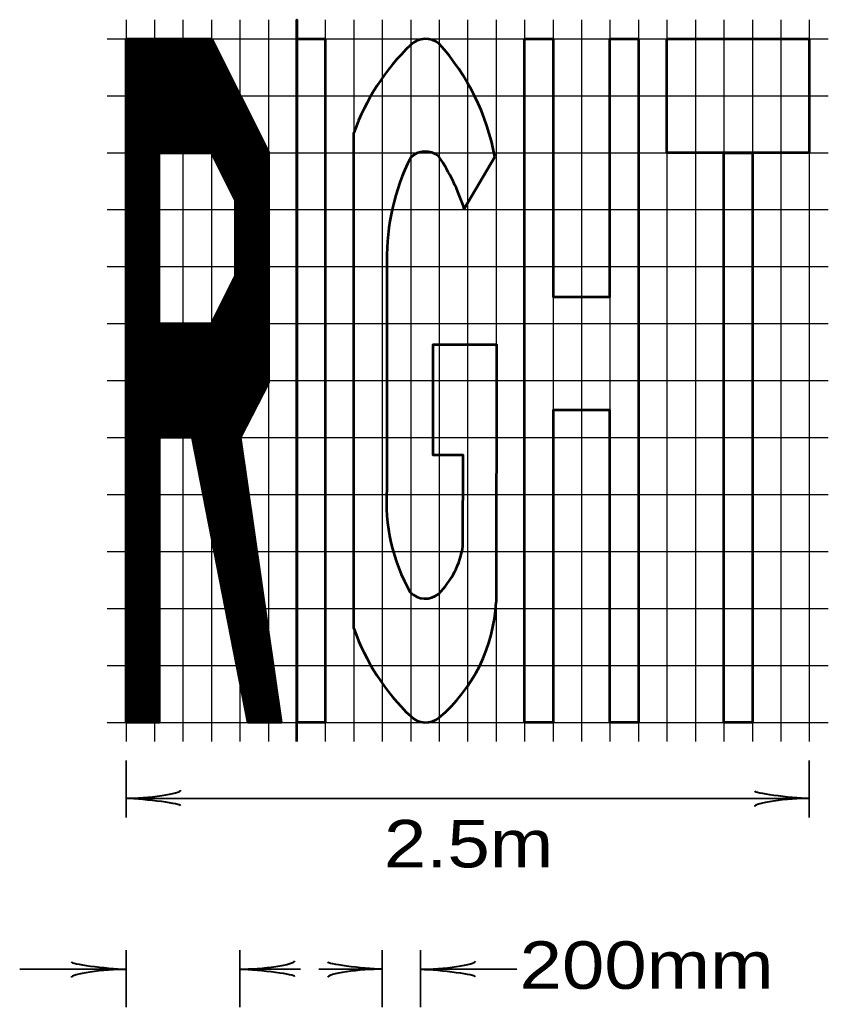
# Model space of a CAD drawing. Extents: x -96 to 617, y -65 to 388.
# Drawn here: x -13.8 to 28.8, y 261.3 to 313.3 of the extents above; entities that cross this region are included whole.
import ezdxf

# ---------------------------------------------------------------- set-up
doc = ezdxf.new("R2010")
doc.units = 0
doc.layers.add('1', color=7, linetype='Continuous', lineweight=53)

msp = doc.modelspace()

# ---------------------------------------------------------------- linework, layer by layer
at = {"layer": '1', "lineweight": 25}
for p, q in [((-8.21, 313.267), (-8.21, 275.267)), ((-6.71, 313.267), (-6.71, 275.267)), ((-5.21, 313.267), (-5.21, 275.267)), ((-3.71, 313.267), (-3.71, 275.267)), ((-2.21, 313.267), (-2.21, 275.267)), ((-0.71, 313.267), (-0.71, 275.267)), ((0.79, 313.267), (0.79, 275.267)), ((2.29, 313.267), (2.29, 275.267)), ((3.79, 313.267), (3.79, 275.267)), ((5.29, 313.267), (5.29, 275.267)), ((6.79, 313.267), (6.79, 275.267)), ((8.29, 313.267), (8.29, 275.267)), ((9.79, 313.267), (9.79, 275.267)), ((11.29, 313.267), (11.29, 275.267)), ((12.79, 313.267), (12.79, 275.267)), ((14.29, 313.267), (14.29, 275.267)), ((15.79, 313.267), (15.79, 275.267)), ((17.29, 313.267), (17.29, 275.267)), ((18.79, 313.267), (18.79, 275.267)), ((20.29, 313.267), (20.29, 275.267)), ((21.79, 313.267), (21.79, 275.267)), ((23.29, 313.267), (23.29, 275.267)), ((24.79, 313.267), (24.79, 275.267)), ((26.29, 313.267), (26.29, 275.267)), ((27.79, 313.267), (27.79, 275.267)), ((-9.21, 312.267), (28.79, 312.267)), ((-9.21, 309.267), (28.79, 309.267)), ((-9.21, 306.267), (28.79, 306.267)), ((-9.21, 303.267), (28.79, 303.267)), ((-9.21, 300.267), (28.79, 300.267)), ((-9.21, 297.267), (28.79, 297.267)), ((-9.21, 294.267), (28.79, 294.267)), ((-9.21, 291.267), (28.79, 291.267)), ((-9.21, 288.267), (28.79, 288.267)), ((-9.21, 285.267), (28.79, 285.267)), ((-9.21, 282.267), (28.79, 282.267)), ((-9.21, 279.267), (28.79, 279.267)), ((-9.21, 276.267), (28.79, 276.267))]:
    msp.add_line(p, q, dxfattribs=at)
at = {"layer": '1'}
for p, q in [((-8.21, 312.122), (-8.064, 312.267)), ((-8.21, 311.945), (-7.888, 312.267)), ((-8.21, 311.769), (-7.711, 312.267)), ((-8.21, 311.592), (-7.534, 312.267)), ((-8.21, 311.415), (-7.357, 312.267)), ((-8.21, 311.238), (-7.181, 312.267)), ((-8.21, 311.061), (-7.004, 312.267)), ((-8.21, 310.885), (-6.827, 312.267)), ((-8.21, 310.708), (-6.65, 312.267)), ((-8.21, 310.531), (-6.473, 312.267)), ((-8.21, 310.354), (-6.297, 312.267)), ((-8.21, 310.178), (-6.12, 312.267)), ((-8.21, 310.001), (-5.943, 312.267)), ((-8.21, 309.824), (-5.766, 312.267)), ((-8.21, 309.647), (-5.59, 312.267)), ((-8.21, 309.47), (-5.413, 312.267)), ((-8.21, 309.294), (-5.236, 312.267)), ((-8.21, 309.117), (-5.059, 312.267)), ((-8.21, 308.94), (-4.882, 312.267)), ((-8.21, 308.763), (-4.706, 312.267)), ((-8.21, 308.587), (-4.529, 312.267)), ((-8.21, 308.41), (-4.352, 312.267)), ((-8.21, 308.233), (-4.175, 312.267)), ((-8.21, 308.056), (-3.999, 312.267)), ((-8.21, 307.879), (-3.822, 312.267)), ((-8.21, 307.703), (-3.688, 312.224)), ((-8.21, 307.526), (-3.629, 312.107)), ((0.79, 312.267), (0.79, 276.267)), ((-8.21, 307.349), (-3.569, 311.989)), ((-8.21, 307.172), (-3.51, 311.872)), ((-8.21, 306.996), (-3.451, 311.754)), ((-8.21, 306.819), (-3.392, 311.637)), ((-8.21, 306.642), (-3.332, 311.519)), ((-8.21, 306.465), (-3.273, 311.402)), ((-8.21, 306.288), (-3.214, 311.284)), ((-8.21, 306.112), (-3.155, 311.167)), ((-8.21, 305.935), (-3.095, 311.049)), ((-8.21, 305.758), (-3.036, 310.932)), ((-8.21, 305.581), (-2.977, 310.814)), ((-8.21, 305.405), (-2.918, 310.697)), ((-8.21, 305.228), (-2.858, 310.579)), ((-8.21, 305.051), (-2.799, 310.462)), ((-8.21, 304.874), (-2.74, 310.344)), ((-8.21, 304.697), (-2.68, 310.227)), ((-8.21, 304.521), (-2.621, 310.109)), ((-6.29, 306.264), (-2.562, 309.991)), ((-6.114, 306.262), (-2.503, 309.874)), ((-5.939, 306.261), (-2.443, 309.757)), ((-5.764, 306.26), (-2.384, 309.639)), ((-5.588, 306.258), (-2.325, 309.522)), ((-5.413, 306.257), (-2.266, 309.404)), ((-5.237, 306.255), (-2.206, 309.286)), ((-5.062, 306.254), (-2.147, 309.169)), ((-4.887, 306.252), (-2.088, 309.051)), ((-4.711, 306.251), (-2.029, 308.934)), ((-4.536, 306.25), (-1.969, 308.816)), ((-4.361, 306.248), (-1.91, 308.699)), ((-4.185, 306.247), (-1.851, 308.581)), ((-4.01, 306.245), (-1.792, 308.464)), ((-3.835, 306.244), (-1.732, 308.346)), ((-3.674, 306.228), (-1.673, 308.229)), ((-3.615, 306.11), (-1.614, 308.111)), ((-3.557, 305.991), (-1.554, 307.994)), ((-3.499, 305.873), (-1.495, 307.876)), ((-3.44, 305.755), (-1.436, 307.759)), ((-3.382, 305.636), (-1.377, 307.641)), ((-3.323, 305.518), (-1.317, 307.524)), ((-3.265, 305.399), (-1.258, 307.406)), ((-3.207, 305.281), (-1.199, 307.289)), ((-3.148, 305.163), (-1.14, 307.171)), ((-3.09, 305.044), (-1.08, 307.054)), ((-3.031, 304.926), (-1.021, 306.936)), ((-2.973, 304.808), (-0.962, 306.819)), ((3.79, 281.219), (3.79, 307.307)), ((-2.915, 304.689), (-0.903, 306.701)), ((-2.856, 304.571), (-0.843, 306.584)), ((-2.798, 304.452), (-0.784, 306.466)), ((-2.739, 304.334), (-0.725, 306.349)), ((-8.21, 304.344), (-6.46, 306.094)), ((-8.21, 304.167), (-6.46, 305.917)), ((-2.681, 304.216), (-0.695, 306.201)), ((-2.623, 304.097), (-0.695, 306.025)), ((-2.564, 303.979), (-0.695, 305.848)), ((11.223, 306.057), (9.615, 303.315)), ((-8.21, 303.99), (-6.46, 305.74)), ((-8.21, 303.814), (-6.46, 305.564)), ((-8.21, 303.637), (-6.46, 305.387)), ((-2.506, 303.861), (-0.695, 305.671)), ((-2.46, 303.73), (-0.695, 305.494)), ((-2.46, 303.553), (-0.695, 305.317)), ((-8.21, 303.46), (-6.46, 305.21)), ((-8.21, 303.283), (-6.46, 305.033)), ((-8.21, 303.106), (-6.46, 304.856)), ((-2.46, 303.376), (-0.695, 305.141)), ((-2.46, 303.2), (-0.695, 304.964)), ((-2.46, 303.023), (-0.695, 304.787)), ((-8.21, 302.93), (-6.46, 304.68)), ((-8.21, 302.753), (-6.46, 304.503)), ((-8.21, 302.576), (-6.46, 304.326)), ((-2.46, 302.846), (-0.695, 304.61)), ((-2.46, 302.669), (-0.695, 304.434)), ((-2.46, 302.493), (-0.695, 304.257)), ((-8.21, 302.399), (-6.46, 304.149)), ((-8.21, 302.223), (-6.46, 303.973)), ((-8.21, 302.046), (-6.46, 303.796)), ((-2.46, 302.316), (-0.695, 304.08)), ((-2.46, 302.139), (-0.695, 303.903)), ((-2.46, 301.962), (-0.695, 303.726)), ((-8.21, 301.869), (-6.46, 303.619)), ((-8.21, 301.692), (-6.46, 303.442)), ((-8.21, 301.515), (-6.46, 303.265)), ((-2.46, 301.785), (-0.695, 303.55)), ((-2.46, 301.609), (-0.695, 303.373)), ((-2.46, 301.432), (-0.695, 303.196)), ((-8.21, 301.339), (-6.46, 303.089)), ((-8.21, 301.162), (-6.46, 302.912)), ((-8.21, 300.985), (-6.46, 302.735)), ((-2.46, 301.255), (-0.695, 303.019)), ((-2.46, 301.078), (-0.695, 302.843)), ((-2.46, 300.901), (-0.695, 302.666)), ((-8.21, 300.808), (-6.46, 302.558)), ((-8.21, 300.632), (-6.46, 302.382)), ((-8.21, 300.455), (-6.46, 302.205)), ((-2.46, 300.725), (-0.695, 302.489)), ((-2.46, 300.548), (-0.695, 302.312)), ((-2.46, 300.371), (-0.695, 302.135)), ((-8.21, 300.278), (-6.46, 302.028)), ((-8.21, 300.101), (-6.46, 301.851)), ((-8.21, 299.924), (-6.46, 301.674)), ((-2.46, 300.194), (-0.695, 301.959)), ((-2.46, 300.018), (-0.695, 301.782)), ((-2.46, 299.841), (-0.695, 301.605)), ((-8.21, 299.748), (-6.46, 301.498)), ((-8.21, 299.571), (-6.46, 301.321)), ((-8.21, 299.394), (-6.46, 301.144)), ((-2.731, 299.216), (-0.695, 301.252)), ((-2.559, 299.564), (-0.695, 301.428)), ((-8.21, 299.217), (-6.46, 300.967)), ((-8.21, 299.041), (-6.46, 300.791)), ((-8.21, 298.864), (-6.46, 300.614)), ((-3.245, 298.172), (-0.695, 300.721)), ((-3.073, 298.52), (-0.695, 300.898)), ((-2.902, 298.868), (-0.695, 301.075)), ((-8.21, 298.687), (-6.46, 300.437)), ((-8.21, 298.51), (-6.46, 300.26)), ((-8.21, 292.677), (-0.695, 300.191)), ((-8.21, 298.334), (-6.46, 300.084)), ((-3.587, 297.476), (-0.695, 300.368)), ((-3.416, 297.824), (-0.695, 300.544)), ((5.54, 300.557), (5.54, 288.557)), ((-8.21, 292.5), (-0.695, 300.014)), ((-8.21, 298.157), (-6.46, 299.907)), ((-8.21, 292.323), (-0.695, 299.837)), ((-8.21, 297.98), (-6.46, 299.73)), ((-8.21, 292.146), (-0.695, 299.661)), ((-8.21, 297.803), (-6.46, 299.553)), ((-8.21, 291.97), (-0.695, 299.484)), ((-8.21, 297.626), (-6.46, 299.376)), ((-8.21, 291.793), (-0.695, 299.307)), ((-8.21, 297.45), (-6.46, 299.2)), ((-8.21, 291.616), (-0.695, 299.13)), ((-8.21, 297.273), (-6.46, 299.023)), ((-8.21, 291.439), (-0.695, 298.954)), ((-8.21, 297.096), (-6.46, 298.846)), ((-8.21, 291.262), (-0.695, 298.777)), ((-8.21, 296.919), (-6.46, 298.669)), ((-8.21, 291.086), (-0.695, 298.6)), ((-8.21, 296.743), (-6.46, 298.493)), ((-8.21, 290.909), (-0.695, 298.423)), ((-8.21, 296.566), (-6.46, 298.316)), ((-8.21, 290.732), (-0.695, 298.246)), ((-8.21, 296.389), (-6.46, 298.139)), ((-8.21, 290.555), (-0.695, 298.07)), ((-8.21, 296.212), (-6.46, 297.962)), ((-8.21, 290.379), (-0.695, 297.893)), ((-8.21, 296.035), (-6.46, 297.785)), ((-8.21, 290.202), (-0.695, 297.716)), ((-8.21, 295.859), (-6.46, 297.609)), ((-8.21, 290.025), (-0.695, 297.539)), ((-8.21, 295.682), (-6.46, 297.432)), ((-8.21, 289.848), (-0.695, 297.363)), ((-8.21, 295.505), (-6.449, 297.265)), ((-8.21, 295.328), (-6.273, 297.264)), ((-8.21, 295.151), (-6.098, 297.263)), ((-8.21, 294.975), (-5.922, 297.262)), ((-8.21, 294.798), (-5.747, 297.261)), ((-8.21, 294.621), (-5.571, 297.26)), ((-8.21, 294.444), (-5.395, 297.259)), ((-8.21, 294.268), (-5.22, 297.258)), ((-8.21, 294.091), (-5.044, 297.257)), ((-8.21, 293.914), (-4.868, 297.255)), ((-8.21, 293.737), (-4.693, 297.254)), ((-8.21, 293.56), (-4.517, 297.253)), ((-8.21, 293.384), (-4.341, 297.252)), ((-8.21, 293.207), (-4.166, 297.251)), ((-8.21, 293.03), (-3.99, 297.25)), ((-8.21, 292.853), (-3.814, 297.249)), ((-8.21, 289.671), (-0.695, 297.186)), ((-6.437, 291.267), (-0.695, 297.009)), ((-6.26, 291.267), (-0.695, 296.832)), ((-6.083, 291.267), (-0.695, 296.655)), ((-5.907, 291.267), (-0.695, 296.479)), ((-5.73, 291.267), (-0.695, 296.302)), ((-5.553, 291.267), (-0.695, 296.125)), ((-5.376, 291.267), (-0.695, 295.948)), ((-5.2, 291.267), (-0.695, 295.772)), ((-5.023, 291.267), (-0.695, 295.595)), ((-4.846, 291.267), (-0.695, 295.418)), ((-4.703, 291.233), (-0.695, 295.241)), ((-4.674, 291.086), (-0.695, 295.065)), ((-4.645, 290.938), (-0.695, 294.888)), ((-4.616, 290.79), (-0.695, 294.711)), ((-4.587, 290.642), (-0.695, 294.534)), ((-4.559, 290.494), (-0.695, 294.357)), ((-4.53, 290.346), (-0.695, 294.181)), ((-4.501, 290.198), (-0.871, 293.828)), ((-4.472, 290.05), (-1.062, 293.46)), ((-4.443, 289.902), (-1.253, 293.093)), ((-4.414, 289.755), (-1.443, 292.725)), ((-4.385, 289.607), (-1.634, 292.358)), ((-4.356, 289.459), (-1.825, 291.99)), ((-8.21, 289.495), (-6.46, 291.245)), ((-4.327, 289.311), (-2.016, 291.623)), ((-4.299, 289.163), (-2.195, 291.267)), ((-8.21, 289.318), (-6.46, 291.068)), ((-8.21, 289.141), (-6.46, 290.891)), ((-8.21, 288.964), (-6.46, 290.714)), ((-4.27, 289.015), (-2.173, 291.112)), ((-4.241, 288.867), (-2.151, 290.958)), ((-4.212, 288.719), (-2.128, 290.803)), ((-8.21, 288.788), (-6.46, 290.538)), ((-8.21, 288.611), (-6.46, 290.361)), ((-8.21, 288.434), (-6.46, 290.184)), ((-4.183, 288.572), (-2.106, 290.649)), ((-4.154, 288.424), (-2.084, 290.494)), ((-4.125, 288.276), (-2.061, 290.34)), ((-4.096, 288.128), (-2.039, 290.185)), ((-8.21, 288.257), (-6.46, 290.007)), ((-8.21, 288.08), (-6.46, 289.83)), ((-8.21, 287.904), (-6.46, 289.654)), ((-4.067, 287.98), (-2.017, 290.031)), ((-4.039, 287.832), (-1.994, 289.876)), ((-4.01, 287.684), (-1.972, 289.722)), ((-8.21, 287.727), (-6.46, 289.477)), ((-8.21, 287.55), (-6.46, 289.3)), ((-8.21, 287.373), (-6.46, 289.123)), ((-3.981, 287.536), (-1.95, 289.567)), ((-3.952, 287.388), (-1.927, 289.413)), ((-3.923, 287.24), (-1.905, 289.258)), ((-8.21, 287.197), (-6.46, 288.947)), ((-8.21, 287.02), (-6.46, 288.77)), ((-3.894, 287.093), (-1.883, 289.104)), ((-3.865, 286.945), (-1.861, 288.949)), ((-3.836, 286.797), (-1.838, 288.795)), ((-3.807, 286.649), (-1.816, 288.64)), ((-8.21, 286.843), (-6.46, 288.593)), ((-8.21, 286.666), (-6.46, 288.416)), ((-8.21, 286.489), (-6.46, 288.239)), ((-3.779, 286.501), (-1.794, 288.486)), ((-3.75, 286.353), (-1.771, 288.332)), ((-3.721, 286.205), (-1.749, 288.177)), ((-8.21, 286.313), (-6.46, 288.063)), ((-8.21, 286.136), (-6.46, 287.886)), ((-8.21, 285.959), (-6.46, 287.709)), ((-3.692, 286.057), (-1.727, 288.023)), ((-3.663, 285.909), (-1.704, 287.868)), ((-3.634, 285.762), (-1.682, 287.714)), ((-8.21, 285.782), (-6.46, 287.532)), ((-8.21, 285.606), (-6.46, 287.356)), ((-8.21, 285.429), (-6.46, 287.179)), ((-3.605, 285.614), (-1.66, 287.559)), ((-3.576, 285.466), (-1.637, 287.405)), ((-3.547, 285.318), (-1.615, 287.25)), ((-3.519, 285.17), (-1.593, 287.096)), ((-8.21, 285.252), (-6.46, 287.002)), ((-8.21, 285.075), (-6.46, 286.825)), ((-8.21, 284.899), (-6.46, 286.649)), ((-3.49, 285.022), (-1.571, 286.941)), ((-3.461, 284.874), (-1.548, 286.787)), ((-3.432, 284.726), (-1.526, 286.632)), ((-8.21, 284.722), (-6.46, 286.472)), ((-8.21, 284.545), (-6.46, 286.295)), ((-8.21, 284.368), (-6.46, 286.118)), ((-3.403, 284.578), (-1.504, 286.478)), ((-3.374, 284.431), (-1.481, 286.323)), ((-3.345, 284.283), (-1.459, 286.169)), ((-3.316, 284.135), (-1.437, 286.014)), ((-8.21, 284.191), (-6.46, 285.941)), ((-8.21, 284.015), (-6.46, 285.765)), ((-8.21, 283.838), (-6.46, 285.588)), ((-3.288, 283.987), (-1.414, 285.86)), ((-3.259, 283.839), (-1.392, 285.705)), ((-3.23, 283.691), (-1.37, 285.551)), ((-8.21, 283.661), (-6.46, 285.411)), ((-8.21, 283.484), (-6.46, 285.234)), ((-8.21, 283.308), (-6.46, 285.058)), ((-3.201, 283.543), (-1.347, 285.397)), ((-3.172, 283.395), (-1.325, 285.242)), ((-3.143, 283.247), (-1.303, 285.088)), ((-8.21, 283.131), (-6.46, 284.881)), ((-8.21, 282.954), (-6.46, 284.704)), ((-8.21, 282.777), (-6.46, 284.527)), ((-3.114, 283.1), (-1.281, 284.933)), ((-3.085, 282.952), (-1.258, 284.779)), ((-3.056, 282.804), (-1.236, 284.624)), ((-3.028, 282.656), (-1.214, 284.47)), ((-8.21, 282.6), (-6.46, 284.35)), ((-8.21, 282.424), (-6.46, 284.174)), ((-8.21, 282.247), (-6.46, 283.997)), ((-2.999, 282.508), (-1.191, 284.315)), ((-2.97, 282.36), (-1.169, 284.161)), ((-2.941, 282.212), (-1.147, 284.006)), ((-8.21, 282.07), (-6.46, 283.82)), ((-8.21, 281.893), (-6.46, 283.643)), ((-8.21, 281.716), (-6.46, 283.466)), ((-2.912, 282.064), (-1.125, 283.852)), ((-2.883, 281.916), (-1.102, 283.697)), ((-2.854, 281.769), (-1.08, 283.543)), ((-8.21, 281.54), (-6.46, 283.29)), ((-8.21, 281.363), (-6.46, 283.113)), ((-8.21, 281.186), (-6.46, 282.936)), ((-2.825, 281.621), (-1.058, 283.388)), ((-2.796, 281.473), (-1.035, 283.234)), ((-2.768, 281.325), (-1.013, 283.079)), ((-2.739, 281.177), (-0.991, 282.925)), ((-8.21, 281.009), (-6.46, 282.759)), ((-8.21, 280.833), (-6.46, 282.583)), ((-8.21, 280.656), (-6.46, 282.406)), ((-2.71, 281.029), (-0.968, 282.771)), ((-2.681, 280.881), (-0.946, 282.616)), ((-2.652, 280.733), (-0.924, 282.462)), ((-8.21, 280.479), (-6.46, 282.229)), ((-8.21, 280.302), (-6.46, 282.052)), ((-8.21, 280.125), (-6.46, 281.875)), ((-2.623, 280.585), (-0.901, 282.307)), ((-2.594, 280.438), (-0.879, 282.153)), ((-2.565, 280.29), (-0.857, 281.998)), ((-2.536, 280.142), (-0.835, 281.844)), ((-8.21, 279.949), (-6.46, 281.699)), ((-8.21, 279.772), (-6.46, 281.522)), ((-8.21, 279.595), (-6.46, 281.345)), ((-2.508, 279.994), (-0.812, 281.689)), ((-2.479, 279.846), (-0.79, 281.535)), ((-2.45, 279.698), (-0.768, 281.38)), ((-8.21, 279.418), (-6.46, 281.168)), ((-8.21, 279.242), (-6.46, 280.992)), ((-8.21, 279.065), (-6.46, 280.815)), ((-2.421, 279.55), (-0.745, 281.226)), ((-2.392, 279.402), (-0.723, 281.071)), ((-2.363, 279.254), (-0.701, 280.917)), ((-8.21, 278.888), (-6.46, 280.638)), ((-8.21, 278.711), (-6.46, 280.461)), ((-8.21, 278.534), (-6.46, 280.284)), ((-2.334, 279.107), (-0.678, 280.762)), ((-2.305, 278.959), (-0.656, 280.608)), ((-2.276, 278.811), (-0.634, 280.453)), ((-2.248, 278.663), (-0.611, 280.299)), ((-8.21, 278.358), (-6.46, 280.108)), ((-8.21, 278.181), (-6.46, 279.931)), ((-2.219, 278.515), (-0.589, 280.145)), ((-2.19, 278.367), (-0.567, 279.99)), ((-2.161, 278.219), (-0.544, 279.836)), ((-8.21, 278.004), (-6.46, 279.754)), ((-8.21, 277.827), (-6.46, 279.577)), ((-8.21, 277.651), (-6.46, 279.401)), ((-2.132, 278.071), (-0.522, 279.681)), ((-2.103, 277.923), (-0.5, 279.527)), ((-2.074, 277.776), (-0.478, 279.372)), ((-8.21, 277.474), (-6.46, 279.224)), ((-8.21, 277.297), (-6.46, 279.047)), ((-8.21, 277.12), (-6.46, 278.87)), ((-2.045, 277.628), (-0.455, 279.218)), ((-2.016, 277.48), (-0.433, 279.063)), ((-1.988, 277.332), (-0.411, 278.909)), ((-1.959, 277.184), (-0.388, 278.754)), ((-8.21, 276.943), (-6.46, 278.693)), ((-8.21, 276.767), (-6.46, 278.517)), ((-8.21, 276.59), (-6.46, 278.34)), ((-1.93, 277.036), (-0.366, 278.6)), ((-1.901, 276.888), (-0.344, 278.445)), ((-1.872, 276.74), (-0.322, 278.291)), ((-8.21, 276.413), (-6.46, 278.163)), ((-8.179, 276.267), (-6.46, 277.986)), ((-8.002, 276.267), (-6.46, 277.81)), ((-1.843, 276.592), (-0.299, 278.136)), ((-1.814, 276.445), (-0.277, 277.982)), ((-1.785, 276.297), (-0.255, 277.827)), ((-7.825, 276.267), (-6.46, 277.633)), ((-7.648, 276.267), (-6.46, 277.456)), ((-7.472, 276.267), (-6.46, 277.279)), ((-1.646, 276.26), (-0.232, 277.673)), ((-1.469, 276.26), (-0.21, 277.519)), ((-1.292, 276.26), (-0.188, 277.364)), ((-1.115, 276.26), (-0.165, 277.21)), ((-7.295, 276.267), (-6.46, 277.102)), ((-7.118, 276.267), (-6.46, 276.926)), ((-6.941, 276.267), (-6.46, 276.749)), ((-0.939, 276.26), (-0.143, 277.055)), ((-0.762, 276.26), (-0.121, 276.901)), ((-0.585, 276.26), (-0.098, 276.746)), ((-6.765, 276.267), (-6.46, 276.572)), ((-6.588, 276.267), (-6.46, 276.395)), ((-0.408, 276.26), (-0.076, 276.592)), ((-0.231, 276.26), (-0.054, 276.437)), ((-0.055, 276.26), (-0.032, 276.283))]:
    msp.add_line(p, q, dxfattribs=at)
at = {"layer": '1', "lineweight": 35}
for p, q in [((-8.21, 274.267), (-8.21, 271.267)), ((27.79, 274.267), (27.79, 271.267)), ((-8.21, 272.267), (27.79, 272.267)), ((-8.21, 264.267), (-8.21, 261.267)), ((-2.21, 264.267), (-2.21, 261.267)), ((5.29, 264.267), (5.29, 261.267)), ((7.313, 264.267), (7.313, 261.267)), ((-13.809, 263.267), (-8.21, 263.267)), ((-2.21, 263.267), (0.988, 263.267)), ((1.949, 263.267), (5.29, 263.267)), ((7.313, 263.267), (12.381, 263.267))]:
    msp.add_line(p, q, dxfattribs=at)
at = {"layer": '1'}
for points in [[(0.79, 275.267), (0.79, 313.267), (0.79, 312.267)], [(0.79, 312.267), (2.29, 312.267), (2.29, 276.267), (0.79, 276.267)], [(9.545, 285.557), (9.554, 290.341), (7.98, 290.341), (7.98, 296.161), (11.315, 296.161), (11.289, 282.604)]]:
    msp.add_lwpolyline(points, dxfattribs=at)
for points in [[(-8.21, 276.267), (-8.21, 312.267), (-3.71, 312.267), (-0.695, 306.29), (-0.695, 294.167), (-2.196, 291.275), (-0.028, 276.26), (-1.778, 276.26), (-4.71, 291.267), (-6.46, 291.267), (-6.46, 276.267)], [(12.79, 312.267), (14.29, 312.267), (14.29, 298.682), (17.29, 298.682), (17.29, 312.267), (18.79, 312.267), (18.79, 276.267), (17.29, 276.267), (17.29, 292.716), (14.29, 292.716), (14.29, 276.267), (12.79, 276.267)], [(20.29, 312.267), (27.79, 312.267), (27.79, 306.267), (20.29, 306.267)], [(-6.46, 297.266), (-6.46, 306.265), (-3.681, 306.243), (-2.46, 303.767), (-2.46, 299.767), (-3.699, 297.248)], [(24.79, 306.267), (24.79, 276.267), (23.29, 276.267), (23.29, 306.267)]]:
    msp.add_lwpolyline(points, close=True, dxfattribs=at)
for centre, radius, start, end in [((7.578, 311.128), 1.13, 50.9473, 134.1805), ((-0.802, 303.825), 12.231, 10.5149, 41.9771), ((14.966, 303.355), 11.854, 133.6087, 160.5287), ((7.557, 305.227), 1.104, 49.7006, 135.4296), ((17.353, 300.749), 11.814, 153.6044, 180.9325), ((-0.895, 299.89), 11.053, 18.048, 33.9839), ((15.016, 287.837), 9.503, 175.6536, 209.8095), ((5.031, 286.268), 4.569, 315.1452, 351.0454), ((7.557, 283.887), 1.104, 224.5704, 310.2994), ((2.805, 283.006), 8.494, 310.2244, 357.2898), ((14.966, 285.17), 11.854, 199.4713, 226.3913), ((7.578, 277.396), 1.129, 225.7902, 309.1188)]:
    msp.add_arc(centre, radius, start, end, dxfattribs=at)
at = {"layer": '1', "lineweight": 40}
for centre, major_axis, ratio, start_param, end_param in [((-7.118, 272.543), (-1.786, -0.156), 0.122415, 0.896353, 3.141593), ((-7.118, 272.543), (-1.786, -0.156), 0.122415, 0.896353, 3.141593), ((26.67, 272.479), (1.756, -0.176), 0.07063, 3.140715, 5.41811), ((26.67, 272.479), (1.756, -0.176), 0.07063, 3.140715, 5.41811), ((-7.089, 272.056), (-1.756, 0.176), 0.07063, 3.140715, 5.41811), ((-7.089, 272.056), (-1.756, 0.176), 0.07063, 3.140715, 5.41811), ((26.699, 271.991), (1.786, 0.156), 0.122415, 0.896353, 3.141593), ((26.699, 271.991), (1.786, 0.156), 0.122415, 0.896353, 3.141593), ((-9.339, 263.476), (1.756, -0.176), 0.07063, 3.140715, 5.41811), ((-1.109, 263.547), (-1.786, -0.156), 0.122415, 0.896353, 3.141593), ((4.161, 263.487), (1.756, -0.176), 0.07063, 3.140715, 5.41811), ((8.413, 263.535), (-1.786, -0.156), 0.122415, 0.896353, 3.141593), ((-9.31, 262.988), (1.786, 0.156), 0.122415, 0.896353, 3.141593), ((-1.08, 263.059), (-1.756, 0.176), 0.07063, 3.140715, 5.41811), ((4.19, 262.999), (1.786, 0.156), 0.122415, 0.896353, 3.141593), ((8.442, 263.047), (-1.756, 0.176), 0.07063, 3.140715, 5.41811)]:
    msp.add_ellipse(centre, major_axis=major_axis, ratio=ratio, start_param=start_param, end_param=end_param, dxfattribs=at)

# ---------------------------------------------------------------- texts
at = {"layer": '1', "width": 1.2}
for s, p in [('2.5m', (5.38, 268.63)), ('200mm', (12.529, 262.237))]:
    msp.add_text(s, height=2.5, dxfattribs=at).set_placement(p)

doc.saveas('drawing.dxf')
